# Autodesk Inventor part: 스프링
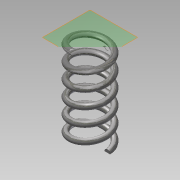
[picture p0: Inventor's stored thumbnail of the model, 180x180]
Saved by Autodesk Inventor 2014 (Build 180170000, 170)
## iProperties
Created: 2015-05
Part Number: 스프링
Material: 강철, 탄소
Document SubType Name: Modeling
Designer: Administrator
Density: 7.87 g/cm^3
Appearance: 반연마
Mass: 11.5039 g
Surface Area: 23.7523 cm^2
Volume: 1.46175 cm^3
Author: Administrator
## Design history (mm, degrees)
sketch "스케치1"
  geometry: L1 (0, 42)-(8, 42); L2 (8, 42)-(8, 0); L3 (8, 0)-(0, 0); L4 (0, 0)-(0, 42); C1 r 1.25 at (8, 0); 1 further point
  constraints: 8 end point, 2 coincident, 2 parallel, 1 centre point, 1 horizontal, 1 perpendicular
  dimensions: "d0" = 16 diameter of L2 L4; "d1" = 42 distance between parallel lines of L1 L3 (derived); "d2" = 2.5 diameter of C1
feature "코일1" sketch "스케치1" pitch "d3" = 10; turns "d5" = 6; dims "d4" = 42 (= d1), "d6" = 0, angle "d7" = 90 deg, angle "d8" = 90 deg, "d9" = 0, "d10" = 0
sketch "스케치2"
  geometry: L1 (-9.25, 0)-(-6.75, 0) reference; 1 further point
  constraints: 1 horizontal alignment
extrude "돌출1" cut sketch "스케치2" stored distance "d11" = 10; taper "d12" = 0 deg
node "작업 평면1"
sketch "스케치3"
  geometry: L1 (9.25, 0)-(6.75, 0) reference; 1 further point
  constraints: 1 horizontal alignment
extrude "돌출2" cut sketch "스케치3" stored distance "d13" = 10; taper "d14" = 0 deg
node "솔리드1"
node "절단 모서리 투영1"
node "절단 모서리 투영2"
